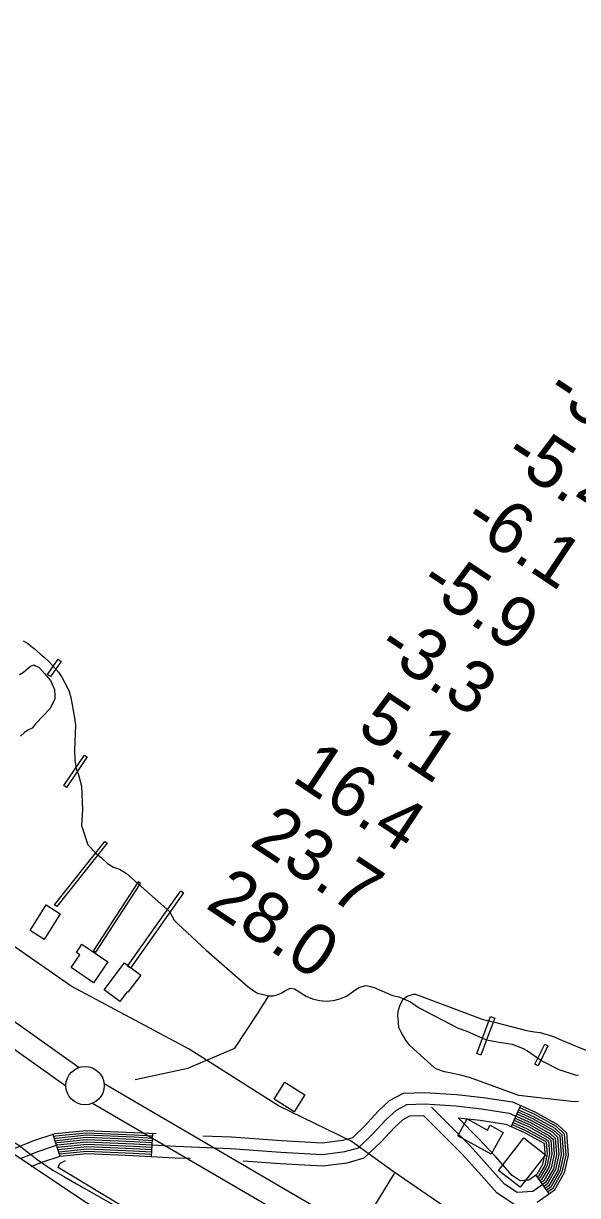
# Model space of a CAD drawing. Extents: x 3161514 to 3199414, y 831166 to 856601.
# Drawn here: x 3180207 to 3180931, y 852425 to 853955 of the extents above; entities that cross this region are included whole.
import ezdxf

# ---------------------------------------------------------------- set-up
doc = ezdxf.new("R2010")
doc.units = 0
for name, color, linetype in [('V-BLDG-OTLN', 7, 'Continuous'), ('V-CHAN-DOCK', 7, 'Continuous'), ('V-LEVE-TOET', 7, 'Continuous'), ('V-RIVR-RANG', 7, 'Continuous'), ('V-ROAD-CNTR', 7, 'Continuous'), ('V-SITE-VEGE', 7, 'Continuous'), ('V-SURV-LINE', 7, 'Continuous'), ('V-TOPO-SHOR', 7, 'Continuous'), ('V-UTIL-LINE', 7, 'Continuous')]:
    doc.layers.add(name, color=color, linetype=linetype)

msp = doc.modelspace()

# ---------------------------------------------------------------- linework, layer by layer
at = {"layer": 'V-BLDG-OTLN'}
for points in [[(3180237, 852804.4), (3180255.5, 852792.9), (3180234.7, 852759.3), (3180216.1, 852770.9)], [(3180317.5, 852730.3), (3180299, 852702.9), (3180269.6, 852722.7), (3180280.9, 852739.4), (3180276.6, 852742.3), (3180283.7, 852753)], [(3180312.9, 852693.7), (3180339.4, 852728.8), (3180360.6, 852712.7), (3180343.7, 852690.4), (3180343, 852690.9), (3180333.4, 852678.2)], [(3180574.8, 852556.6), (3180560.9, 852534.5), (3180534.7, 852550.9), (3180548.6, 852573.1)], [(3180786.5, 852525), (3180813.2, 852510.2), (3180816.7, 852516.7), (3180833.6, 852507.3), (3180817.9, 852478.9), (3180774.4, 852503)], [(3180855.7, 852435.8), (3180827.5, 852457.7), (3180860.6, 852500.2), (3180888.8, 852478.3)]]:
    msp.add_lwpolyline(points, close=True, dxfattribs=at)
at = {"layer": 'V-CHAN-DOCK'}
for points in [[(3180238.9, 853105.1), (3180252.8, 853125), (3180256.7, 853122.2), (3180242.7, 853102.4), (3180238.9, 853105.1)], [(3180260.3, 852960.2), (3180287.3, 853000), (3180290.8, 852997.7), (3180263.8, 852957.8), (3180260.3, 852960.2)], [(3180316.7, 852885.2), (3180251, 852802.4), (3180248.2, 852804.5), (3180313.9, 852887.4), (3180316.7, 852885.2)], [(3180301.9, 852742.9), (3180360.4, 852832.4), (3180357.2, 852834.4), (3180298.7, 852745), (3180301.9, 852742.9)], [(3180343.5, 852724.6), (3180412.8, 852822.8), (3180416.6, 852820.1), (3180347.3, 852722), (3180343.5, 852724.6)], [(3180806.7, 852630.6), (3180817.2, 852658.7), (3180822.6, 852656.6), (3180812, 852628.4)], [(3180812, 852628.4), (3180804.6, 852608.5), (3180799.2, 852610.6), (3180806.7, 852630.6)], [(3180875, 852596.5), (3180887.9, 852622.5), (3180891.9, 852620.4), (3180879.1, 852594.5), (3180875, 852596.5)]]:
    msp.add_lwpolyline(points, dxfattribs=at)
at = {"layer": 'V-LEVE-TOET'}
for points in [[(3180643.2, 852490.5), (3180635.4, 852496.2), (3180540.3, 852542.2), (3180423.9, 852616.2), (3180269.9, 852698.4), (3180148.9, 852782.5), (3180075.8, 852847.5), (3180013.1, 852901.3), (3180000.9, 852908.1), (3179994.3, 852911.2)], [(3180172.2, 852505.5), (3180180, 852501.2), (3180200.2, 852491.8), (3180222.9, 852474.1)], [(3181272.1, 852116.2), (3181228.7, 852143.9), (3181064, 852230.7), (3180932, 852303.1), (3180817.6, 852369.1), (3180690.2, 852456.5), (3180643.2, 852490.5)], [(3180222.9, 852474.1), (3180225.4, 852472.2), (3180246, 852458.1), (3180261.2, 852449.3), (3180276.7, 852440.2), (3180378.3, 852382.9), (3180599.4, 852247.2), (3180781.4, 852135.7), (3180979.3, 852013.2)]]:
    msp.add_lwpolyline(points, dxfattribs=at)
at = {"layer": 'V-ROAD-CNTR'}
for p, q in [((3180856.2, 852542.5), (3180844, 852515.1)), ((3180245.8, 852504.9), (3180255.1, 852476.3)), ((3180375.9, 852506.1), (3180374.2, 852476.2)), ((3180893.8, 852427.2), (3180876.5, 852451.7))]:
    msp.add_line(p, q, dxfattribs=at)
for points in [[(3177592.2, 854789.9), (3177971.4, 854316.2), (3178263.7, 853942.1), (3178396, 853775.7), (3178430.3, 853732.9), (3178457, 853704.8), (3178482.7, 853679.1), (3178527.4, 853641.6), (3178608, 853580.7), (3178927.2, 853358), (3179165.4, 853188.9), (3179528.5, 852937.7), (3180018.6, 852597.4), (3180287.5, 852417.1), (3180694.2, 852166.9), (3181125.4, 851896.4)], [(3180441.5, 852503.1), (3180479.1, 852501.6), (3180544.4, 852496.8), (3180597.2, 852493.9), (3180623.9, 852497.3), (3180637.2, 852501), (3180652.5, 852515.5), (3180670.4, 852535.1), (3180685.4, 852548.9), (3180703.7, 852558.7), (3180731.3, 852559.7), (3180772.8, 852557), (3180807.3, 852553), (3180845.7, 852547.2), (3180875.9, 852533.8), (3180904.5, 852517.8), (3180916.1, 852507), (3180918.3, 852477.7), (3180913.2, 852454.5), (3180900.2, 852431.8), (3180877.8, 852415.9)], [(3180203.5, 852473.4), (3180226.2, 852482.7), (3180252.1, 852491.1), (3180289.9, 852495.1), (3180351.4, 852492.5), (3180406.3, 852489.4), (3180478.2, 852486.6), (3180543.4, 852481.8), (3180597.8, 852478.8), (3180626.9, 852482.6), (3180644.8, 852487.5), (3180663.2, 852505), (3180681, 852524.4), (3180694.2, 852536.6), (3180707.7, 852543.9), (3180731, 852544.7), (3180771.4, 852542), (3180805.4, 852538.1), (3180841.5, 852532.7), (3180869.2, 852520.3), (3180895.6, 852505.6), (3180901.6, 852500.1), (3180903.2, 852478.8), (3180899.1, 852460), (3180888.8, 852442.1), (3180872.4, 852430.5), (3180851.9, 852428.8), (3180835.4, 852439.9), (3180812.5, 852465.7), (3180790.8, 852489.3), (3180754.8, 852525.8), (3180740, 852540.4)], [(3180851.4, 852531.6), (3180870.5, 852523), (3180897.4, 852508.1), (3180904.5, 852501.4), (3180906.2, 852478.5), (3180901.9, 852458.9), (3180891.1, 852440), (3180886.9, 852437)], [(3180852.6, 852534.3), (3180871.9, 852525.7), (3180899.2, 852510.5), (3180907.4, 852502.8), (3180909.2, 852478.3), (3180904.8, 852457.8), (3180893.4, 852437.9), (3180888.6, 852434.6)], [(3180853.8, 852537), (3180873.2, 852528.4), (3180900.9, 852513), (3180910.3, 852504.2), (3180912.3, 852478.1), (3180907.6, 852456.7), (3180895.7, 852435.9), (3180890.3, 852432.1)], [(3180855, 852539.8), (3180874.5, 852531.1), (3180902.7, 852515.4), (3180913.2, 852505.6), (3180915.3, 852477.9), (3180910.4, 852455.6), (3180897.9, 852433.8), (3180892.1, 852429.7)], [(3180494.2, 852470.4), (3180542.4, 852466.8), (3180598.3, 852463.8), (3180629.8, 852467.8), (3180652.4, 852474.1), (3180673.9, 852494.5), (3180691.7, 852513.8), (3180703, 852524.3), (3180711.8, 852529), (3180729.6, 852529.6)], [(3180848, 852413.4), (3180825.4, 852428.5), (3180801.4, 852455.7), (3180779.9, 852478.9), (3180744.2, 852515.2), (3180729.6, 852529.6)], [(3180775.1, 852526.5), (3180803.4, 852523.3), (3180837.2, 852518.2), (3180862.5, 852506.9), (3180886.7, 852493.4), (3180887, 852493.1), (3180888.1, 852479.8), (3180884.9, 852465.4), (3180877.5, 852452.4), (3180867.1, 852445.1), (3180855.9, 852444.2), (3180845.4, 852451.2), (3180823.7, 852475.8), (3180801.6, 852499.6), (3180775.1, 852526.5)], [(3180845.2, 852517.9), (3180863.8, 852509.6), (3180888.5, 852495.9), (3180889.9, 852494.5), (3180891.1, 852479.6), (3180887.8, 852464.3), (3180879.7, 852450.3), (3180878.2, 852449.3)], [(3180846.5, 852520.6), (3180865.1, 852512.3), (3180890.3, 852498.3), (3180892.9, 852495.9), (3180894.1, 852479.4), (3180890.6, 852463.3), (3180882, 852448.3), (3180879.9, 852446.8)], [(3180847.7, 852523.3), (3180866.5, 852515), (3180892, 852500.7), (3180895.8, 852497.3), (3180897.1, 852479.2), (3180893.4, 852462.2), (3180884.3, 852446.2), (3180881.7, 852444.4)], [(3180848.9, 852526.1), (3180867.8, 852517.6), (3180893.8, 852503.2), (3180898.7, 852498.7), (3180900.2, 852479), (3180896.3, 852461.1), (3180886.6, 852444.1), (3180883.4, 852441.9)], [(3180850.1, 852528.8), (3180869.2, 852520.3), (3180895.6, 852505.6), (3180901.6, 852500.1), (3180903.2, 852478.8), (3180899.1, 852460), (3180888.8, 852442.1), (3180885.1, 852439.5)], [(3180189.1, 852483.7), (3180221, 852496.8), (3180249, 852505.9), (3180289.4, 852510.1), (3180352.1, 852507.5), (3180380.9, 852505.9)], [(3180246.7, 852502), (3180249.6, 852502.9), (3180289.5, 852507.1), (3180352, 852504.5), (3180375.7, 852503.1)], [(3180247.7, 852499.2), (3180250.2, 852500), (3180289.6, 852504.1), (3180351.9, 852501.5), (3180375.6, 852500.1)], [(3180248.6, 852496.3), (3180250.8, 852497), (3180289.7, 852501.1), (3180351.7, 852498.5), (3180375.4, 852497.1)], [(3180249.5, 852493.4), (3180251.5, 852494.1), (3180289.8, 852498.1), (3180351.6, 852495.5), (3180375.2, 852494.2)], [(3180250.4, 852490.6), (3180252.1, 852491.1), (3180289.9, 852495.1), (3180351.4, 852492.5), (3180375.1, 852491.2)], [(3180251.4, 852487.7), (3180252.7, 852488.2), (3180290, 852492.1), (3180351.3, 852489.5), (3180374.9, 852488.2)], [(3180252.3, 852484.9), (3180253.3, 852485.2), (3180290.1, 852489.1), (3180351.1, 852486.5), (3180374.7, 852485.2)], [(3180253.2, 852482), (3180254, 852482.3), (3180290.2, 852486.1), (3180351, 852483.5), (3180374.6, 852482.2)], [(3180217.6, 852463), (3180231.4, 852468.6), (3180255.2, 852476.4), (3180290.3, 852480.1), (3180350.7, 852477.5), (3180405.6, 852474.4), (3180425.4, 852473.7)], [(3180254.1, 852479.2), (3180254.6, 852479.3), (3180290.3, 852483.1), (3180350.8, 852480.5), (3180374.4, 852479.2)]]:
    msp.add_lwpolyline(points, dxfattribs=at)
at = {"layer": 'V-SITE-VEGE'}
for p, q in [((3180211.2, 853111.5), (3180216.9, 853115.9)), ((3180216.9, 853115.9), (3180221.2, 853117.9)), ((3180221.2, 853117.9), (3180223.1, 853116.6)), ((3180223.1, 853116.6), (3180227.5, 853114.8)), ((3180227.5, 853114.8), (3180235.1, 853106.7)), ((3180202.5, 853105.2), (3180207.5, 853108.3)), ((3180207.5, 853108.3), (3180211.2, 853111.5)), ((3180235.1, 853106.7), (3180242.7, 853097.3)), ((3180242.7, 853097.3), (3180247.9, 853085.4)), ((3180247.9, 853085.4), (3180248.5, 853077.9)), ((3180248.6, 853073.5), (3180242.4, 853060.9)), ((3180248.5, 853077.9), (3180248.6, 853073.5)), ((3180242.4, 853060.9), (3180223.7, 853041.3)), ((3180223.7, 853041.3), (3180218.8, 853035)), ((3180208.8, 853029.3), (3180203.8, 853024.8)), ((3180213.1, 853032.4), (3180208.8, 853029.3)), ((3180218.8, 853035), (3180213.1, 853032.4))]:
    msp.add_line(p, q, dxfattribs=at)
msp.add_lwpolyline([(3180932, 852547.8), (3180926.7, 852547.2), (3180854, 852555.7), (3180789.5, 852579.2), (3180777.9, 852582.3), (3180766, 852584.8), (3180756.9, 852586.5), (3180747, 852590.1), (3180743.9, 852591.8), (3180712, 852620.9), (3180706.6, 852627.9), (3180700.4, 852638.1), (3180697.5, 852644.6), (3180696.4, 852656.5), (3180696, 852659.4), (3180696.6, 852665.9), (3180699.1, 852674.2), (3180703, 852681.6), (3180708.2, 852685.5), (3180716.4, 852688.1), (3180719.4, 852687.9), (3180806.4, 852655.1), (3180826, 852650.5), (3180864.2, 852640.7), (3180874.6, 852638.8), (3180881.8, 852637.8), (3180897.8, 852633), (3180911.2, 852627.5), (3180977.2, 852599.8)], dxfattribs=at)
at = {"layer": 'V-SURV-LINE'}
for points in [[(3179814.4, 852923.6), (3180280.3, 852592.2)], [(3180262.9, 852567.8), (3179797, 852899.1)], [(3180312.7, 852571.3), (3180841.6, 852262.2)], [(3180826.5, 852236.3), (3180297.5, 852545.4)]]:
    msp.add_lwpolyline(points, dxfattribs=at)
msp.add_circle((3180287.9, 852568.5), 25, dxfattribs=at)
at = {"layer": 'V-TOPO-SHOR'}
msp.add_line((3180806.7, 852630.6), (3180812, 852628.4), dxfattribs=at)
for points in [[(3180207, 853149.1), (3180213.1, 853145.8), (3180222, 853138.6), (3180229.2, 853132.1), (3180234.7, 853127.9), (3180241.7, 853121.1)], [(3180241.7, 853121.1), (3180253.1, 853108.2), (3180257.4, 853101.8), (3180264.8, 853087.9), (3180267, 853083.1), (3180269.5, 853075.2), (3180274.3, 853048.6), (3180275.5, 853039.2), (3180274.1, 853006.8), (3180274.5, 852993), (3180276.5, 852982.6), (3180279.2, 852974.2), (3180283.3, 852959.4), (3180284.4, 852928.5), (3180283.1, 852908.3), (3180291.6, 852882.7), (3180301.8, 852872), (3180309.3, 852865.7), (3180317.1, 852858.6), (3180325.1, 852853.5), (3180333, 852851.3), (3180341.9, 852845.5), (3180398.3, 852795.8), (3180404, 852784.7), (3180408.9, 852779.9), (3180446, 852745.2), (3180500.3, 852698), (3180505.5, 852694.2), (3180511.8, 852690.1), (3180513.1, 852689.4), (3180522.1, 852687.1), (3180527.6, 852685.8), (3180533.4, 852685.9), (3180538.8, 852686.9), (3180543.7, 852689.1), (3180550.7, 852693.4), (3180556.4, 852695.6), (3180561.2, 852694.7), (3180576.3, 852685.5), (3180584.9, 852681.7), (3180593.8, 852679.5), (3180602.8, 852678.9), (3180612, 852679.8), (3180620.4, 852681.7), (3180629.2, 852685.1), (3180641.4, 852694), (3180645.7, 852696.8), (3180649.4, 852698.1), (3180654.5, 852699.1), (3180660.4, 852697.9), (3180665.1, 852696.5), (3180689.2, 852686.1), (3180697.3, 852684.6)], [(3180353.3, 852576.6), (3180422.1, 852591.5), (3180483.4, 852617.5), (3180513.1, 852662.1), (3180527.6, 852685.8)], [(3180697.3, 852684.6), (3180712.5, 852678), (3180723.2, 852670.3), (3180775.1, 852643.7), (3180786.1, 852639.4), (3180806.7, 852630.6)], [(3180812, 852628.4), (3180825.6, 852625.5), (3180845.2, 852622.5), (3180858.8, 852617.5), (3180865.4, 852614.1), (3180884.3, 852601), (3180906.1, 852589.7), (3180927.6, 852582.6), (3180932, 852582.2)], [(3180985, 852010), (3180678.5, 852197.6), (3180658, 852205.1), (3180650.6, 852219.9), (3180360.8, 852396.4), (3180253, 852461.5), (3180254.9, 852467), (3180262.3, 852470.7)]]:
    msp.add_lwpolyline(points, dxfattribs=at)
at = {"layer": 'V-UTIL-LINE'}
msp.add_line((3180582.5, 852275.5), (3180691.6, 852453.7), dxfattribs=at)

# ---------------------------------------------------------------- texts
at = {"layer": 'V-RIVR-RANG'}
for s, p in [('-3.9', (3180886.4, 853467.8)), ('-5.4', (3180831.5, 853384.2)), ('-6.1', (3180778.4, 853299.4)), ('-5.9', (3180721.1, 853217.4)), ('-3.3', (3180666.2, 853133.8)), ('5.1', (3180640.8, 853030.7)), ('16.4', (3180556, 852966.9)), ('23.7', (3180501, 852883.5)), ('28.0', (3180443.4, 852801.6))]:
    msp.add_text(s, height=67, rotation=326.4283, dxfattribs=at).set_placement(p)

doc.saveas('drawing.dxf')
